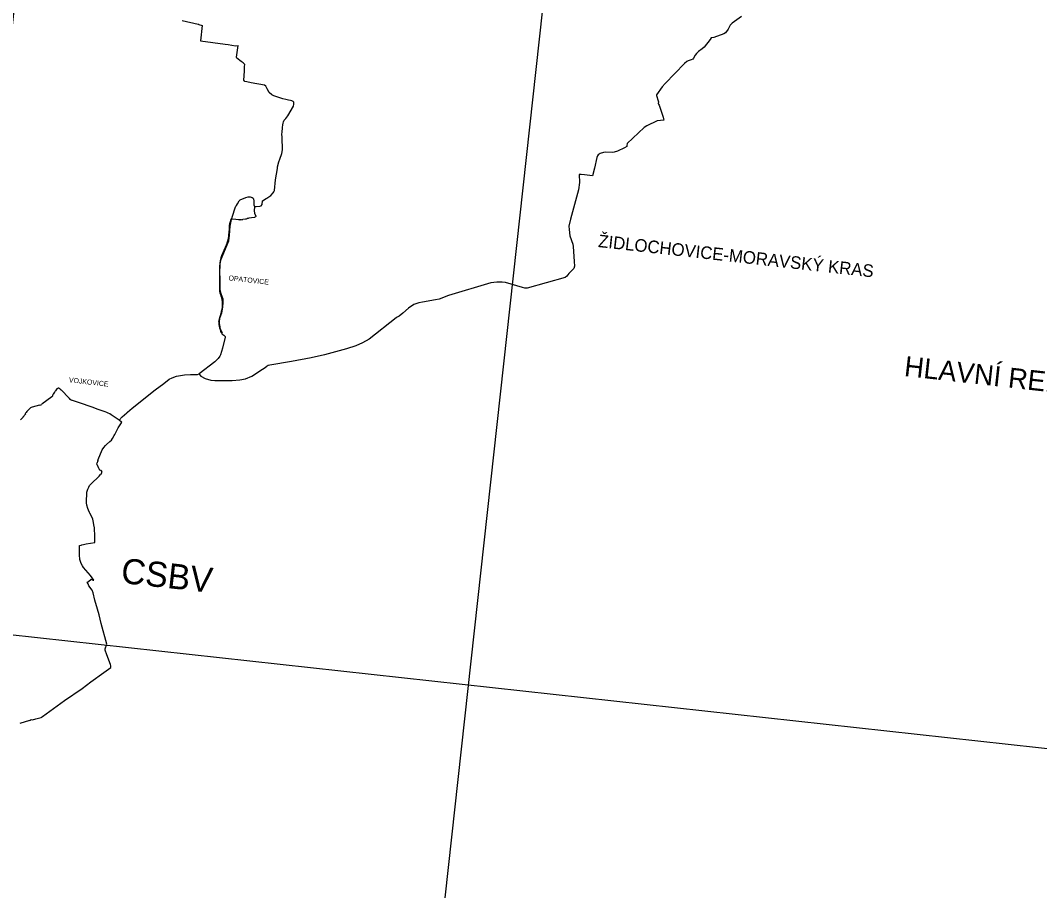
# Model space of a CAD drawing. Extents: x -678204 to -526855, y -1228851 to -1110393.
# Drawn here: x -600114 to -587930, y -1182450 to -1172050 of the extents above; entities that cross this region are included whole.
import ezdxf

# ---------------------------------------------------------------- set-up
doc = ezdxf.new("R2010")
doc.units = 0
for name, color, linetype in [('00_n_cyklo popisy', 7, 'Continuous'), ('00_n_cyklo popisy ostatni', 7, 'Continuous'), ('00_n_cyklo prujezdne rekreacni hlavni', 7, 'Continuous'), ('00_n_cyklo prujezdne rekreacni vedlejsi', 7, 'Continuous'), ('00_n_cyklo studie rekreacni hlavni', 7, 'Continuous'), ('00_n_cyklo studie rekreacni vedlejsi', 7, 'Continuous'), ('00_n_cyklo trasovani rekreacni hlavni', 7, 'Continuous'), ('00_n_cyklo trasovani rekreacni vedlejsi', 7, 'Continuous'), ('00_n_legenda popisy', 7, 'Continuous'), ('_HELP BIG', 7, 'Continuous')]:
    doc.layers.add(name, color=color, linetype=linetype)

msp = doc.modelspace()

# ---------------------------------------------------------------- linework, layer by layer
at = {"layer": '00_n_cyklo prujezdne rekreacni hlavni'}
for p, q in [((-598180, -1172050), (-597989, -1172097)), ((-597979, -1172100), (-597940, -1172111)), ((-597940, -1172111), (-597961, -1172294)), ((-599189, -1177313), (-599201, -1177344)), ((-599201, -1177352), (-599187, -1177382)), ((-599189, -1177303), (-599188, -1177308)), ((-599186, -1177295), (-599188, -1177300)), ((-599183, -1177389), (-599173, -1177414)), ((-599167, -1177420), (-599152, -1177427)), ((-599143, -1177462), (-599156, -1177479)), ((-599147, -1177432), (-599141, -1177447))]:
    msp.add_line(p, q, dxfattribs=at)
for points in [[(-597961, -1172294), (-597665, -1172335), (-597631, -1172340), (-597544, -1172353), (-597511, -1172351)], [(-597702, -1175777), (-597709, -1175769), (-597718, -1175748), (-597724, -1175727), (-597727, -1175712), (-597734, -1175672), (-597734, -1175641), (-597724, -1175598), (-597706, -1175545), (-597692, -1175476), (-597688, -1175417), (-597691, -1175381), (-597712, -1175319), (-597722, -1175292), (-597726, -1175258), (-597725, -1175121), (-597728, -1175079), (-597725, -1174960), (-597712, -1174902), (-597622, -1174684), (-597614, -1174622), (-597608, -1174509), (-597589, -1174428), (-597556, -1174316), (-597547, -1174291), (-597538, -1174271), (-597532, -1174262), (-597519, -1174242), (-597500, -1174207), (-597488, -1174193), (-597419, -1174166), (-597390, -1174160), (-597366, -1174160), (-597345, -1174165), (-597333, -1174173), (-597326, -1174183), (-597324, -1174209), (-597324, -1174255), (-597317, -1174273), (-597296, -1174276), (-597253, -1174271), (-597234, -1174267), (-597224, -1174249), (-597221, -1174208), (-597176, -1174180), (-597168, -1174176), (-597132, -1174152), (-597121, -1174142), (-597093, -1174112), (-597083, -1174098), (-597075, -1174083), (-597065, -1173954), (-597042, -1173820), (-597039, -1173799), (-597024, -1173742), (-597014, -1173710), (-596989, -1173642), (-596981, -1173599), (-596985, -1173450), (-596987, -1173404), (-596985, -1173388), (-596980, -1173329), (-596977, -1173299), (-596974, -1173279), (-596970, -1173262), (-596959, -1173244), (-596940, -1173223), (-596917, -1173192), (-596850, -1173074), (-596843, -1173051), (-596844, -1173029), (-596852, -1173020), (-596860, -1173015), (-596868, -1173011), (-596884, -1173008), (-596910, -1173004), (-596942, -1172997), (-596975, -1172988), (-597026, -1172972), (-597084, -1172951), (-597108, -1172940), (-597141, -1172913), (-597164, -1172870), (-597180, -1172837), (-597197, -1172825), (-597356, -1172795), (-597406, -1172786), (-597432, -1172779), (-597443, -1172763), (-597436, -1172657), (-597433, -1172600), (-597432, -1172577), (-597451, -1172558), (-597476, -1172540), (-597528, -1172502), (-597532, -1172491), (-597511, -1172351)], [(-597702, -1175777), (-597707, -1175786), (-597704, -1175798), (-597682, -1175812), (-597668, -1175822), (-597666, -1175828), (-597665, -1175836), (-597699, -1175966), (-597722, -1176048), (-597730, -1176064), (-597748, -1176089), (-597769, -1176112), (-597791, -1176132), (-597976, -1176276)], [(-599186, -1177296), (-599135, -1177182), (-599118, -1177156), (-599097, -1177131), (-599084, -1177118), (-599043, -1177083), (-599026, -1177065), (-599011, -1177046), (-598993, -1177012), (-598985, -1177000), (-598943, -1176920), (-598915, -1176871), (-598901, -1176853), (-598926, -1176834), (-598934, -1176828), (-598898, -1176789), (-598843, -1176741), (-598833, -1176732), (-598776, -1176685), (-598501, -1176465), (-598400, -1176388), (-598335, -1176337), (-598298, -1176320), (-598248, -1176303), (-598201, -1176295), (-598153, -1176288), (-598079, -1176281), (-598037, -1176281), (-598005, -1176283), (-597996, -1176282), (-597976, -1176276)], [(-600116, -1180450), (-600052, -1180431), (-600012, -1180419), (-600008, -1180418), (-599995, -1180412), (-599985, -1180407), (-599969, -1180410), (-599930, -1180398), (-599866, -1180380), (-599860, -1180378), (-599850, -1180371), (-599586, -1180177), (-599375, -1180033), (-599273, -1179956), (-599118, -1179845), (-599034, -1179782), (-599032, -1179771), (-599032, -1179762), (-599037, -1179748), (-599079, -1179631), (-599099, -1179575), (-599099, -1179561), (-599080, -1179504), (-599147, -1179256), (-599174, -1179154), (-599193, -1179087), (-599223, -1178978), (-599245, -1178893), (-599255, -1178860), (-599294, -1178809), (-599303, -1178783), (-599315, -1178765), (-599300, -1178755), (-599266, -1178729), (-599253, -1178737), (-599248, -1178739), (-599237, -1178738), (-599277, -1178686), (-599358, -1178587), (-599371, -1178568), (-599387, -1178542), (-599397, -1178517), (-599403, -1178492), (-599405, -1178477), (-599408, -1178452), (-599409, -1178407), (-599407, -1178326), (-599389, -1178321), (-599379, -1178318), (-599360, -1178314), (-599328, -1178307), (-599223, -1178290), (-599222, -1178238), (-599222, -1178228), (-599224, -1178181), (-599226, -1178151), (-599229, -1178112), (-599231, -1178101), (-599238, -1178050), (-599248, -1178012), (-599254, -1177993), (-599284, -1177938), (-599287, -1177931), (-599287, -1177931), (-599300, -1177904), (-599307, -1177884), (-599318, -1177842), (-599322, -1177816), (-599323, -1177787), (-599321, -1177713), (-599318, -1177688), (-599309, -1177651), (-599297, -1177627), (-599286, -1177610), (-599268, -1177590), (-599173, -1177498), (-599157, -1177479)]]:
    msp.add_lwpolyline(points, dxfattribs=at)
for centre, radius, start, end in [((-598049, -1172340), 250, 73.6995, 76.1466), ((-599192, -1177348), 10, 158.6205, 205.5215), ((-599184, -1177302), 5, 155.8291, 182.9997), ((-599198, -1177309), 10, 338.6205, 2.9997), ((-599367, -1177468), 200, 23.0953, 25.5215), ((-599162, -1177409), 12, 203.0953, 244.1746), ((-599157, -1177436), 10, 22.5369, 64.1746), ((-599155, -1177453), 15, 323.0308, 22.5369)]:
    msp.add_arc(centre, radius, start, end, dxfattribs=at)
at = {"layer": '00_n_cyklo prujezdne rekreacni vedlejsi'}
msp.add_line((-600057, -1176749), (-600058, -1176750), dxfattribs=at)
for points in [[(-591495, -1172004), (-591606, -1172084), (-591627, -1172108), (-591654, -1172155), (-591685, -1172197), (-591706, -1172209), (-591825, -1172255), (-591848, -1172260), (-591855, -1172260), (-591867, -1172280), (-591939, -1172369), (-591962, -1172390), (-592006, -1172421), (-592032, -1172445), (-592046, -1172464), (-592067, -1172500), (-592077, -1172512), (-592096, -1172521), (-592132, -1172533), (-592147, -1172541), (-592175, -1172565), (-592405, -1172804), (-592440, -1172846), (-592510, -1172939), (-592511, -1172949), (-592488, -1173010), (-592487, -1173025), (-592489, -1173042), (-592485, -1173051), (-592478, -1173062), (-592429, -1173205), (-592424, -1173226), (-592423, -1173243), (-592463, -1173245), (-592500, -1173252), (-592626, -1173309), (-592656, -1173332), (-592859, -1173522), (-592863, -1173546), (-592866, -1173556), (-592894, -1173574), (-592977, -1173615), (-593014, -1173626), (-593041, -1173628), (-593120, -1173623), (-593145, -1173627), (-593182, -1173641), (-593206, -1173656), (-593213, -1173670), (-593221, -1173690), (-593252, -1173818), (-593274, -1173906), (-593369, -1173896), (-593412, -1173890), (-593434, -1173891), (-593429, -1173986), (-593443, -1174075), (-593539, -1174426), (-593558, -1174509), (-593555, -1174550), (-593547, -1174623), (-593508, -1174724), (-593504, -1174752), (-593493, -1174933), (-593490, -1174988), (-593498, -1175016), (-593512, -1175033), (-593558, -1175076), (-593582, -1175106), (-593602, -1175123), (-594054, -1175249), (-594085, -1175250), (-594112, -1175242), (-594315, -1175183), (-594355, -1175179), (-594419, -1175178), (-594488, -1175186), (-594995, -1175339), (-595109, -1175380), (-595151, -1175389), (-595308, -1175417), (-595351, -1175427), (-595409, -1175446), (-595476, -1175488), (-595543, -1175549), (-595586, -1175585), (-595610, -1175595), (-595620, -1175604), (-595946, -1175858), (-596024, -1175905), (-596102, -1175939), (-596217, -1175977), (-596479, -1176047), (-596639, -1176083), (-596874, -1176125), (-597132, -1176169), (-597152, -1176176), (-597177, -1176189)], [(-597976, -1176278), (-597955, -1176302), (-597906, -1176328), (-597839, -1176349), (-597790, -1176355), (-597584, -1176352), (-597489, -1176345), (-597422, -1176332), (-597347, -1176301), (-597218, -1176220), (-597177, -1176189)], [(-599706, -1176493), (-599722, -1176516)], [(-599694, -1176477), (-599698, -1176483)], [(-599736, -1176549), (-599859, -1176638)], [(-599728, -1176530), (-599730, -1176540)], [(-600009, -1176695), (-600036, -1176725), (-600046, -1176736), (-600057, -1176749)], [(-599884, -1176650), (-599973, -1176674)]]:
    msp.add_lwpolyline(points, dxfattribs=at)
for centre, radius, start, end in [((-599298, -1176782), 500, 143.1943, 144.7069), ((-599745, -1176537), 15, 305.9043, 349.3596), ((-599694, -1176537), 35, 144.7069, 169.3596), ((-599954, -1176746), 75, 104.9545, 137.1558), ((-599903, -1176578), 75, 284.9545, 305.9043)]:
    msp.add_arc(centre, radius, start, end, dxfattribs=at)
at = {"layer": '00_n_cyklo studie rekreacni hlavni'}
for p, q in [((-597599, -1174428), (-597611, -1174470)), ((-597480, -1174432), (-597498, -1174433)), ((-597423, -1174424), (-597456, -1174429)), ((-597301, -1174394), (-597309, -1174400)), ((-597619, -1174523), (-597621, -1174603)), ((-597643, -1174708), (-597704, -1174854)), ((-597733, -1174991), (-597735, -1175267)), ((-597728, -1175306), (-597714, -1175344)), ((-597710, -1175526), (-597739, -1175622))]:
    msp.add_line(p, q, dxfattribs=at)
for points in [[(-597317, -1174273), (-597320, -1174325), (-597317, -1174352), (-597299, -1174389), (-597301, -1174394)], [(-597501, -1174433), (-597538, -1174430), (-597595, -1174426)], [(-597320, -1174405), (-597381, -1174415)]]:
    msp.add_lwpolyline(points, dxfattribs=at)
for centre, radius, start, end in [((-597596, -1174429), 3, 85.3662, 163.9265), ((-597500, -1174418), 15, 265.9013, 274.4866), ((-597503, -1174133), 300, 274.4866, 279.0827), ((-597471, -1174127), 300, 279.0827, 283.4718), ((-597331, -1174711), 300, 99.658, 103.4718), ((-597324, -1174380), 25, 279.658, 306.0908), ((-597409, -1174528), 210, 163.9265, 178.6394), ((-597910, -1174596), 290, 337.2485, 358.6394), ((-597370, -1174994), 363, 157.2485, 179.5474), ((-597622, -1175268), 113, 179.5474, 199.8796), ((-597984, -1175442), 287, 343.0657, 19.8796), ((-597634, -1175655), 110, 163.0657, 185.8134), ((-597353, -1175626), 392, 185.8134, 197.7661), ((-597622, -1175712), 110, 197.7661, 208.7595), ((-597731, -1175772), 15, 354.892, 28.7595), ((-597707, -1175774), 9.13, 174.892, 267.0277)]:
    msp.add_arc(centre, radius, start, end, dxfattribs=at)
at = {"layer": '00_n_cyklo studie rekreacni vedlejsi'}
for p, q in [((-600051, -1176756), (-600084, -1176792)), ((-600058, -1176750), (-600051, -1176756))]:
    msp.add_line(p, q, dxfattribs=at)
for points in [[(-599677, -1176454), (-599694, -1176477)], [(-599638, -1176459), (-599649, -1176450)], [(-599517, -1176579), (-599527, -1176570), (-599547, -1176550), (-599612, -1176483), (-599628, -1176467)], [(-599101, -1176728), (-599196, -1176696), (-599244, -1176678), (-599304, -1176657), (-599359, -1176637), (-599408, -1176621), (-599501, -1176588)], [(-600086, -1176794), (-600114, -1176825)], [(-598933, -1176828), (-599030, -1176763)]]:
    msp.add_lwpolyline(points, dxfattribs=at)
for centre, radius, start, end in [((-599661, -1176466), 20, 52.3311, 143.1943), ((-599699, -1176538), 100, 44.7947, 52.3311), ((-599484, -1176541), 50, 228.7335, 250.6733), ((-599197, -1177012), 300, 56.0883, 71.2271), ((-599714, -1177128), 500, 137.8037, 138.1188)]:
    msp.add_arc(centre, radius, start, end, dxfattribs=at)
at = {"layer": '00_n_cyklo trasovani rekreacni hlavni'}
for p, q in [((-598180, -1172050), (-597989, -1172097)), ((-597979, -1172100), (-597940, -1172111)), ((-597940, -1172111), (-597961, -1172294)), ((-597599, -1174428), (-597611, -1174470)), ((-597480, -1174432), (-597498, -1174433)), ((-597423, -1174424), (-597456, -1174429)), ((-597301, -1174394), (-597309, -1174400)), ((-597619, -1174523), (-597621, -1174603)), ((-597643, -1174708), (-597704, -1174854)), ((-597733, -1174991), (-597735, -1175267)), ((-597728, -1175306), (-597714, -1175344)), ((-597710, -1175526), (-597739, -1175622)), ((-599189, -1177313), (-599201, -1177344)), ((-599201, -1177352), (-599187, -1177382)), ((-599189, -1177303), (-599188, -1177308)), ((-599186, -1177295), (-599188, -1177300)), ((-599183, -1177389), (-599173, -1177414)), ((-599167, -1177420), (-599152, -1177427)), ((-599143, -1177462), (-599156, -1177479)), ((-599147, -1177432), (-599141, -1177447))]:
    msp.add_line(p, q, dxfattribs=at)
for points in [[(-597961, -1172294), (-597665, -1172335), (-597631, -1172340), (-597544, -1172353), (-597511, -1172351)], [(-597702, -1175777), (-597709, -1175769), (-597718, -1175748), (-597724, -1175727), (-597727, -1175712), (-597734, -1175672), (-597734, -1175641), (-597724, -1175598), (-597706, -1175545), (-597692, -1175476), (-597688, -1175417), (-597691, -1175381), (-597712, -1175319), (-597722, -1175292), (-597726, -1175258), (-597725, -1175121), (-597728, -1175079), (-597725, -1174960), (-597712, -1174902), (-597622, -1174684), (-597614, -1174622), (-597608, -1174509), (-597589, -1174428), (-597556, -1174316), (-597547, -1174291), (-597538, -1174271), (-597532, -1174262), (-597519, -1174242), (-597500, -1174207), (-597488, -1174193), (-597419, -1174166), (-597390, -1174160), (-597366, -1174160), (-597345, -1174165), (-597333, -1174173), (-597326, -1174183), (-597324, -1174209), (-597324, -1174255), (-597317, -1174273), (-597296, -1174276), (-597253, -1174271), (-597234, -1174267), (-597224, -1174249), (-597221, -1174208), (-597176, -1174180), (-597168, -1174176), (-597132, -1174152), (-597121, -1174142), (-597093, -1174112), (-597083, -1174098), (-597075, -1174083), (-597065, -1173954), (-597042, -1173820), (-597039, -1173799), (-597024, -1173742), (-597014, -1173710), (-596989, -1173642), (-596981, -1173599), (-596985, -1173450), (-596987, -1173404), (-596985, -1173388), (-596980, -1173329), (-596977, -1173299), (-596974, -1173279), (-596970, -1173262), (-596959, -1173244), (-596940, -1173223), (-596917, -1173192), (-596850, -1173074), (-596843, -1173051), (-596844, -1173029), (-596852, -1173020), (-596860, -1173015), (-596868, -1173011), (-596884, -1173008), (-596910, -1173004), (-596942, -1172997), (-596975, -1172988), (-597026, -1172972), (-597084, -1172951), (-597108, -1172940), (-597141, -1172913), (-597164, -1172870), (-597180, -1172837), (-597197, -1172825), (-597356, -1172795), (-597406, -1172786), (-597432, -1172779), (-597443, -1172763), (-597436, -1172657), (-597433, -1172600), (-597432, -1172577), (-597451, -1172558), (-597476, -1172540), (-597528, -1172502), (-597532, -1172491), (-597511, -1172351)], [(-597317, -1174273), (-597320, -1174325), (-597317, -1174352), (-597299, -1174389), (-597301, -1174394)], [(-597501, -1174433), (-597538, -1174430), (-597595, -1174426)], [(-597320, -1174405), (-597381, -1174415)], [(-597702, -1175777), (-597707, -1175786), (-597704, -1175798), (-597682, -1175812), (-597668, -1175822), (-597666, -1175828), (-597665, -1175836), (-597699, -1175966), (-597722, -1176048), (-597730, -1176064), (-597748, -1176089), (-597769, -1176112), (-597791, -1176132), (-597976, -1176276)], [(-599186, -1177296), (-599135, -1177182), (-599118, -1177156), (-599097, -1177131), (-599084, -1177118), (-599043, -1177083), (-599026, -1177065), (-599011, -1177046), (-598993, -1177012), (-598985, -1177000), (-598943, -1176920), (-598915, -1176871), (-598901, -1176853), (-598926, -1176834), (-598934, -1176828), (-598898, -1176789), (-598843, -1176741), (-598833, -1176732), (-598776, -1176685), (-598501, -1176465), (-598400, -1176388), (-598335, -1176337), (-598298, -1176320), (-598248, -1176303), (-598201, -1176295), (-598153, -1176288), (-598079, -1176281), (-598037, -1176281), (-598005, -1176283), (-597996, -1176282), (-597976, -1176276)], [(-600116, -1180450), (-600052, -1180431), (-600012, -1180419), (-600008, -1180418), (-599995, -1180412), (-599985, -1180407), (-599969, -1180410), (-599930, -1180398), (-599866, -1180380), (-599860, -1180378), (-599850, -1180371), (-599586, -1180177), (-599375, -1180033), (-599273, -1179956), (-599118, -1179845), (-599034, -1179782), (-599032, -1179771), (-599032, -1179762), (-599037, -1179748), (-599079, -1179631), (-599099, -1179575), (-599099, -1179561), (-599080, -1179504), (-599147, -1179256), (-599174, -1179154), (-599193, -1179087), (-599223, -1178978), (-599245, -1178893), (-599255, -1178860), (-599294, -1178809), (-599303, -1178783), (-599315, -1178765), (-599300, -1178755), (-599266, -1178729), (-599253, -1178737), (-599248, -1178739), (-599237, -1178738), (-599277, -1178686), (-599358, -1178587), (-599371, -1178568), (-599387, -1178542), (-599397, -1178517), (-599403, -1178492), (-599405, -1178477), (-599408, -1178452), (-599409, -1178407), (-599407, -1178326), (-599389, -1178321), (-599379, -1178318), (-599360, -1178314), (-599328, -1178307), (-599223, -1178290), (-599222, -1178238), (-599222, -1178228), (-599224, -1178181), (-599226, -1178151), (-599229, -1178112), (-599231, -1178101), (-599238, -1178050), (-599248, -1178012), (-599254, -1177993), (-599284, -1177938), (-599287, -1177931), (-599287, -1177931), (-599300, -1177904), (-599307, -1177884), (-599318, -1177842), (-599322, -1177816), (-599323, -1177787), (-599321, -1177713), (-599318, -1177688), (-599309, -1177651), (-599297, -1177627), (-599286, -1177610), (-599268, -1177590), (-599173, -1177498), (-599157, -1177479)]]:
    msp.add_lwpolyline(points, dxfattribs=at)
for centre, radius, start, end in [((-598049, -1172340), 250, 73.6995, 76.1466), ((-597596, -1174429), 3, 85.3662, 163.9265), ((-597500, -1174418), 15, 265.9013, 274.4866), ((-597503, -1174133), 300, 274.4866, 279.0827), ((-597471, -1174127), 300, 279.0827, 283.4718), ((-597331, -1174711), 300, 99.658, 103.4718), ((-597324, -1174380), 25, 279.658, 306.0908), ((-597409, -1174528), 210, 163.9265, 178.6394), ((-597910, -1174596), 290, 337.2485, 358.6394), ((-597370, -1174994), 363, 157.2485, 179.5474), ((-597622, -1175268), 113, 179.5474, 199.8796), ((-597984, -1175442), 287, 343.0657, 19.8796), ((-597634, -1175655), 110, 163.0657, 185.8134), ((-597353, -1175626), 392, 185.8134, 197.7661), ((-597622, -1175712), 110, 197.7661, 208.7595), ((-597731, -1175772), 15, 354.892, 28.7595), ((-597707, -1175774), 9.13, 174.892, 267.0277), ((-599192, -1177348), 10, 158.6205, 205.5215), ((-599184, -1177302), 5, 155.8291, 182.9997), ((-599198, -1177309), 10, 338.6205, 2.9997), ((-599367, -1177468), 200, 23.0953, 25.5215), ((-599162, -1177409), 12, 203.0953, 244.1746), ((-599157, -1177436), 10, 22.5369, 64.1746), ((-599155, -1177453), 15, 323.0308, 22.5369)]:
    msp.add_arc(centre, radius, start, end, dxfattribs=at)
at = {"layer": '00_n_cyklo trasovani rekreacni vedlejsi'}
for p, q in [((-600057, -1176749), (-600058, -1176750)), ((-600051, -1176756), (-600084, -1176792)), ((-600058, -1176750), (-600051, -1176756))]:
    msp.add_line(p, q, dxfattribs=at)
for points in [[(-591495, -1172004), (-591606, -1172084), (-591627, -1172108), (-591654, -1172155), (-591685, -1172197), (-591706, -1172209), (-591825, -1172255), (-591848, -1172260), (-591855, -1172260), (-591867, -1172280), (-591939, -1172369), (-591962, -1172390), (-592006, -1172421), (-592032, -1172445), (-592046, -1172464), (-592067, -1172500), (-592077, -1172512), (-592096, -1172521), (-592132, -1172533), (-592147, -1172541), (-592175, -1172565), (-592405, -1172804), (-592440, -1172846), (-592510, -1172939), (-592511, -1172949), (-592488, -1173010), (-592487, -1173025), (-592489, -1173042), (-592485, -1173051), (-592478, -1173062), (-592429, -1173205), (-592424, -1173226), (-592423, -1173243), (-592463, -1173245), (-592500, -1173252), (-592626, -1173309), (-592656, -1173332), (-592859, -1173522), (-592863, -1173546), (-592866, -1173556), (-592894, -1173574), (-592977, -1173615), (-593014, -1173626), (-593041, -1173628), (-593120, -1173623), (-593145, -1173627), (-593182, -1173641), (-593206, -1173656), (-593213, -1173670), (-593221, -1173690), (-593252, -1173818), (-593274, -1173906), (-593369, -1173896), (-593412, -1173890), (-593434, -1173891), (-593429, -1173986), (-593443, -1174075), (-593539, -1174426), (-593558, -1174509), (-593555, -1174550), (-593547, -1174623), (-593508, -1174724), (-593504, -1174752), (-593493, -1174933), (-593490, -1174988), (-593498, -1175016), (-593512, -1175033), (-593558, -1175076), (-593582, -1175106), (-593602, -1175123), (-594054, -1175249), (-594085, -1175250), (-594112, -1175242), (-594315, -1175183), (-594355, -1175179), (-594419, -1175178), (-594488, -1175186), (-594995, -1175339), (-595109, -1175380), (-595151, -1175389), (-595308, -1175417), (-595351, -1175427), (-595409, -1175446), (-595476, -1175488), (-595543, -1175549), (-595586, -1175585), (-595610, -1175595), (-595620, -1175604), (-595946, -1175858), (-596024, -1175905), (-596102, -1175939), (-596217, -1175977), (-596479, -1176047), (-596639, -1176083), (-596874, -1176125), (-597132, -1176169), (-597152, -1176176), (-597177, -1176189)], [(-597976, -1176278), (-597955, -1176302), (-597906, -1176328), (-597839, -1176349), (-597790, -1176355), (-597584, -1176352), (-597489, -1176345), (-597422, -1176332), (-597347, -1176301), (-597218, -1176220), (-597177, -1176189)], [(-599706, -1176493), (-599722, -1176516)], [(-599694, -1176477), (-599698, -1176483)], [(-599677, -1176454), (-599694, -1176477)], [(-599638, -1176459), (-599649, -1176450)], [(-599517, -1176579), (-599527, -1176570), (-599547, -1176550), (-599612, -1176483), (-599628, -1176467)], [(-599736, -1176549), (-599859, -1176638)], [(-599728, -1176530), (-599730, -1176540)], [(-599101, -1176728), (-599196, -1176696), (-599244, -1176678), (-599304, -1176657), (-599359, -1176637), (-599408, -1176621), (-599501, -1176588)], [(-600009, -1176695), (-600036, -1176725), (-600046, -1176736), (-600057, -1176749)], [(-599884, -1176650), (-599973, -1176674)], [(-600086, -1176794), (-600114, -1176825)], [(-598933, -1176828), (-599030, -1176763)]]:
    msp.add_lwpolyline(points, dxfattribs=at)
for centre, radius, start, end in [((-599298, -1176782), 500, 143.1943, 144.7069), ((-599661, -1176466), 20, 52.3311, 143.1943), ((-599699, -1176538), 100, 44.7947, 52.3311), ((-599745, -1176537), 15, 305.9043, 349.3596), ((-599694, -1176537), 35, 144.7069, 169.3596), ((-599484, -1176541), 50, 228.7335, 250.6733), ((-599954, -1176746), 75, 104.9545, 137.1558), ((-599903, -1176578), 75, 284.9545, 305.9043), ((-599197, -1177012), 300, 56.0883, 71.2271), ((-599714, -1177128), 500, 137.8037, 138.1188)]:
    msp.add_arc(centre, radius, start, end, dxfattribs=at)
at = {"layer": '_HELP BIG'}
for points in [[(-572713, -1182415), (-601001, -1179309), (-598788, -1159164), (-570501, -1162270)], [(-616542, -1192691), (-613436, -1164403), (-593291, -1166615), (-596397, -1194903)]]:
    msp.add_lwpolyline(points, close=True, dxfattribs=at)

# ---------------------------------------------------------------- texts
at = {"layer": '00_n_cyklo popisy'}
msp.add_text('CSBV', height=300, rotation=353.6836, dxfattribs=at).set_placement((-598920, -1178772))
at = {"layer": '00_n_cyklo popisy ostatni'}
for s, height, p in [('ŽIDLOCHOVICE-MORAVSKÝ KRAS', 150, (-593212, -1174758)), ('OPATOVICE', 60, (-597628, -1175156)), ('VOJKOVICE', 60, (-599536, -1176375))]:
    msp.add_text(s, height=height, rotation=353.6836, dxfattribs=at).set_placement(p)
at = {"layer": '00_n_legenda popisy'}
msp.add_text('HLAVNÍ REKREAČNÍ TRASY (PODMÍNĚNĚ PRŮJEZDNÉ ÚSEKY K PROVĚŘENÍ) ', height=240, rotation=353.6836, dxfattribs=at).set_placement((-589556, -1176299))

doc.saveas('drawing.dxf')
